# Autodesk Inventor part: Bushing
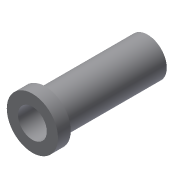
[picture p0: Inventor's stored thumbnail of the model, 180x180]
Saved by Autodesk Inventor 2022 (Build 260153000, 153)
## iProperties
Created: 2002-02
Part Number: Bushing
Document SubType Name: Modeling
Designer: ***
Density: 1 g/cm^3
Material: Generic
Appearance: Default
Control State: 0
Master: False
Checked Out: False
Shininess: 77.0
Length Units: 11269
Angle Units: 11279
Time Units: 11290
Mass Units: 11283
Length Display Precision: 3
Angle Display Precision: 2
Density: 0.0
Volumn: 0.0
Area: 0.0
PropertySet Name: Model Information
Author: ***
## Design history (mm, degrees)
sketch "Sketch1"
  geometry: L1 (6.25, 50.44)-(6.25, 5.44); L2 (6.25, 5.44)-(10.625, 5.44); L3 (10.625, 5.44)-(10.625, 10.44); L4 (10.625, 10.44)-(8.125, 10.44); L5 (8.125, 10.44)-(8.125, 50.44); L6 (8.125, 50.44)-(6.25, 50.44); L7 (0.625, 34.884)-(0.625, 0)
  constraints: 14 end point, 4 parallel, 2 perpendicular, 1 vertical
  dimensions: "d0" = 20 diameter of L3 L7; "d1" = 11.25 diameter of L1 L7; "d2" = 15 diameter of L5 L7; "d4" = 5 distance of L2.end L3.end; "d5" = 45 distance of L1.start L1.end
revolve "Revolution1" sketch "Sketch1" stored, may be unused: angle "d3" = 90 deg
body "Solid1"
